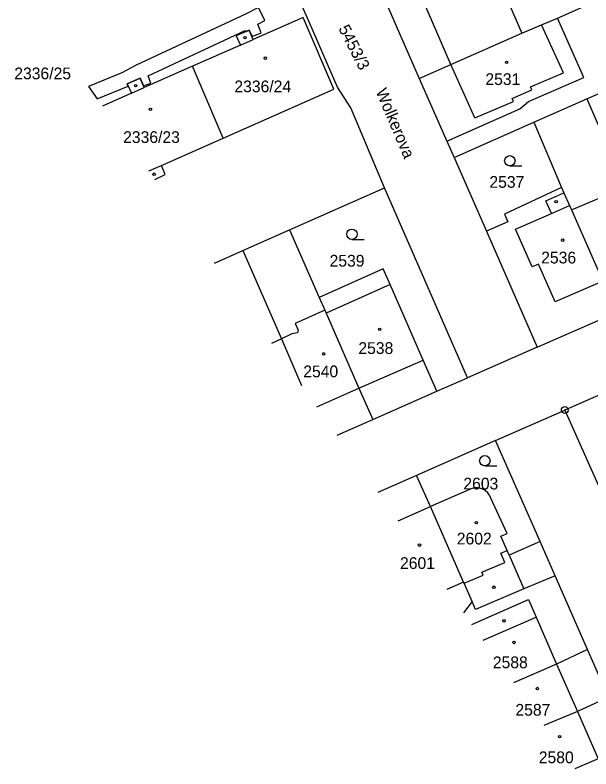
# Model space of a CAD drawing. Extents: x -821458 to -820266, y -1071458 to -1069826.
# Drawn here: x -820847.1 to -820763.7, y -1071320.8 to -1071211.7 of the extents above; entities that cross this region are included whole.
import ezdxf

# ---------------------------------------------------------------- set-up
doc = ezdxf.new("R2010")
doc.units = 0
for name, color, linetype in [('Vrstva 1', 7, 'Continuous'), ('Vrstva 13', 7, 'Continuous'), ('Vrstva 2', 7, 'Continuous'), ('Vrstva 3', 7, 'Continuous'), ('Vrstva 4', 7, 'Continuous'), ('Vrstva 5', 7, 'Continuous'), ('Vrstva 7', 7, 'Continuous'), ('Vrstva 8', 7, 'Continuous')]:
    doc.layers.add(name, color=color, linetype=linetype)

msp = doc.modelspace()

# ---------------------------------------------------------------- linework, layer by layer
at = {"layer": 'Vrstva 1'}
for p, q in [((-820783.95, -1071218.81), (-820790.93, -1071202.76)), ((-820768.53, -1071212.08), (-820752.85, -1071205.14)), ((-820783.95, -1071218.81), (-820773.66, -1071214.29)), ((-820816.91, -1071229.46), (-820821.37, -1071219.04)), ((-820788.57, -1071220.85), (-820783.95, -1071218.81)), ((-820788.57, -1071220.85), (-820784.55, -1071229.93)), ((-820764.28, -1071223.77), (-820757.43, -1071220.74)), ((-820771.93, -1071227.16), (-820764.28, -1071223.77)), ((-820783.5, -1071232.29), (-820771.93, -1071227.16)), ((-820771.93, -1071227.16), (-820767.92, -1071236.61)), ((-820784.55, -1071229.93), (-820783.5, -1071232.29)), ((-820783.5, -1071232.29), (-820778.81, -1071242.96)), ((-820807.32, -1071242.73), (-820793.58, -1071236.65)), ((-820781.53, -1071264.15), (-820793.58, -1071236.65)), ((-820814.1, -1071245.75), (-820807.32, -1071242.73)), ((-820807.32, -1071242.73), (-820803.01, -1071252.53)), ((-820778.81, -1071242.96), (-820771.47, -1071259.73)), ((-820818.19, -1071247.56), (-820814.1, -1071245.75)), ((-820771.47, -1071259.73), (-820759.98, -1071254.72)), ((-820771.47, -1071259.73), (-820781.53, -1071264.15)), ((-820749.12, -1071260.8), (-820767.46, -1071268.84)), ((-820786.01, -1071266.12), (-820781.53, -1071264.15)), ((-820795.25, -1071270.19), (-820786.01, -1071266.12)), ((-820777.49, -1071273.25), (-820767.46, -1071268.84)), ((-820767.46, -1071268.84), (-820760.37, -1071284.81)), ((-820800.44, -1071272.47), (-820795.25, -1071270.19)), ((-820777.49, -1071273.25), (-820788.93, -1071278.29)), ((-820771.05, -1071287.86), (-820777.49, -1071273.25)), ((-820788.93, -1071278.29), (-820794.53, -1071280.76)), ((-820786.92, -1071282.82), (-820788.93, -1071278.29)), ((-820781.01, -1071280.22), (-820786.92, -1071282.82)), ((-820768.86, -1071292.83), (-820771.05, -1071287.86)), ((-820764.16, -1071303.5), (-820768.86, -1071292.83)), ((-820780.88, -1071296.55), (-820782.11, -1071298.19)), ((-820761.12, -1071310.4), (-820764.16, -1071303.5))]:
    msp.add_line(p, q, dxfattribs=at)
for points in [[(-820796.98, -1071151.09), (-820799.19, -1071153.08), (-820801.78, -1071155.4), (-820804.28, -1071158.47), (-820806.33, -1071161.63), (-820807.71, -1071165.19), (-820808.34, -1071171.22), (-820808.11, -1071173.69), (-820807.37, -1071176.5), (-820806.77, -1071178.58), (-820806.01, -1071180.77), (-820788.57, -1071220.85)], [(-820793.58, -1071236.65), (-820798.44, -1071225.1), (-820800.39, -1071222.09), (-820804.84, -1071211.76), (-820807.79, -1071205.27), (-820809.61, -1071200.07), (-820811.76, -1071194.82), (-820812.77, -1071194.08), (-820813.94, -1071193.87), (-820836.17, -1071203.63), (-820846.32, -1071208.08)], [(-820780.65, -1071198.21), (-820777.6, -1071205.22), (-820776.77, -1071207.14), (-820773.66, -1071214.29)], [(-820816.91, -1071229.46), (-820800.9, -1071222.39), (-820805.35, -1071211.99), (-820812.57, -1071215.18), (-820813.16, -1071213.83), (-820815.03, -1071214.64), (-820814.43, -1071216), (-820821.37, -1071219.04)], [(-820784.55, -1071229.93), (-820773.96, -1071225.23), (-820772.71, -1071224.15), (-820764.69, -1071220.67), (-820768.53, -1071212.08)], [(-820773.66, -1071214.29), (-820770.82, -1071213.09), (-820768.53, -1071212.08)], [(-820821.37, -1071219.04), (-820828.34, -1071222.14), (-820828.93, -1071220.8), (-820830.81, -1071221.62), (-820830.21, -1071222.97), (-820834.4, -1071224.82)], [(-820764.28, -1071223.77), (-820759.48, -1071234.8), (-820754.18, -1071246.75), (-820752.2, -1071251.29)], [(-820826.81, -1071235.46), (-820825.31, -1071234.75), (-820825.87, -1071233.42), (-820816.91, -1071229.46)], [(-820767.92, -1071236.61), (-820776.2, -1071240.49), (-820775.71, -1071241.59), (-820778.81, -1071242.96)], [(-820767.92, -1071236.61), (-820767.59, -1071237.39), (-820766.79, -1071239.2), (-820766.51, -1071239.84), (-820761.95, -1071250.16), (-820759.98, -1071254.72)], [(-820814.1, -1071245.75), (-820808.48, -1071258.54), (-820805.56, -1071265.28)], [(-820786.01, -1071266.12), (-820787.96, -1071261.62), (-820792.74, -1071250.67), (-820793.74, -1071248.39), (-820803.01, -1071252.53)], [(-820803.01, -1071252.53), (-820802.21, -1071254.37), (-820802.01, -1071254.82), (-820797.26, -1071265.69), (-820795.25, -1071270.19)], [(-820778.17, -1071281.6), (-820778.36, -1071281.17), (-820778.63, -1071280.8), (-820778.98, -1071280.49), (-820779.21, -1071280.34), (-820779.64, -1071280.17), (-820780.09, -1071280.08), (-820780.56, -1071280.1), (-820781.01, -1071280.22)], [(-820771.05, -1071287.86), (-820775.51, -1071289.82), (-820775.79, -1071289.18), (-820776.74, -1071287.11), (-820775.83, -1071286.69), (-820778.17, -1071281.6)], [(-820780.88, -1071296.55), (-820782.04, -1071293.91), (-820782.12, -1071293.73), (-820786.92, -1071282.82)], [(-820768.86, -1071292.83), (-820773.37, -1071294.74), (-820780.37, -1071297.7), (-820780.88, -1071296.55)], [(-820764.16, -1071303.5), (-820768.65, -1071305.6), (-820774.91, -1071308.3)], [(-820761.12, -1071310.4), (-820765.64, -1071312.47), (-820770.48, -1071314.51)], [(-820758.1, -1071317.28), (-820762.63, -1071319.34), (-820766.01, -1071320.79)]]:
    msp.add_lwpolyline(points, dxfattribs=at)
at = {"layer": 'Vrstva 13'}
msp.add_line((-820836.4, -1071222), (-820835.15, -1071223.77), dxfattribs=at)
msp.add_lwpolyline([(-820835.15, -1071223.77), (-820830.67, -1071221.93), (-820830.81, -1071221.62), (-820828.93, -1071220.8), (-820828.46, -1071221.88), (-820827.39, -1071221.49), (-820827.77, -1071220.43), (-820813.76, -1071213.89), (-820813.69, -1071214.06), (-820813.16, -1071213.83), (-820812.75, -1071214.77), (-820811.4, -1071214.23), (-820811.9, -1071212.98), (-820810.87, -1071212.46), (-820811.83, -1071210.58), (-820813.68, -1071211.52), (-820829.54, -1071218.93), (-820831.6, -1071220.03), (-820836.4, -1071222)], dxfattribs=at)
at = {"layer": 'Vrstva 3'}
for p, q in [((-820775.42, -1071233.5), (-820773.67, -1071233.5)), ((-820798.28, -1071244.14), (-820796.53, -1071244.14)), ((-820779.04, -1071276.92), (-820777.29, -1071276.92))]:
    msp.add_line(p, q, dxfattribs=at)
for centre in [(-820775.42, -1071232.75), (-820798.28, -1071243.39), (-820779.04, -1071276.17)]:
    msp.add_circle(centre, 0.75, dxfattribs=at)
at = {"layer": 'Vrstva 4'}
for p, q in [((-820767.67, -1071220.01), (-820770.82, -1071213.09)), ((-820814.43, -1071216), (-820812.57, -1071215.18)), ((-820780.47, -1071226.54), (-820783.95, -1071218.81)), ((-820772.41, -1071222.03), (-820767.67, -1071220.01)), ((-820830.21, -1071222.97), (-820828.34, -1071222.14)), ((-820772.22, -1071222.48), (-820772.41, -1071222.03)), ((-820775.09, -1071223.71), (-820772.22, -1071222.48)), ((-820780.47, -1071226.54), (-820774.9, -1071224.16)), ((-820774.9, -1071224.16), (-820775.09, -1071223.71)), ((-820827.69, -1071234.22), (-820825.87, -1071233.42)), ((-820770.21, -1071238.55), (-820767.59, -1071237.39)), ((-820769.41, -1071240.36), (-820770.21, -1071238.55)), ((-820766.51, -1071239.84), (-820762.48, -1071238.15)), ((-820769.41, -1071240.36), (-820766.79, -1071239.2)), ((-820774.6, -1071242.66), (-820769.41, -1071240.36)), ((-820772.21, -1071248.1), (-820774.6, -1071242.66)), ((-820771.29, -1071247.71), (-820772.21, -1071248.1)), ((-820768.88, -1071253.19), (-820771.29, -1071247.71)), ((-820792.74, -1071250.67), (-820802.01, -1071254.82)), ((-820761.95, -1071250.16), (-820768.88, -1071253.19)), ((-820802.21, -1071254.37), (-820806.51, -1071256.29)), ((-820806.51, -1071256.29), (-820806.07, -1071257.28)), ((-820806.07, -1071257.28), (-820806.17, -1071257.66)), ((-820806.97, -1071257.8), (-820808.48, -1071258.54)), ((-820806.17, -1071257.66), (-820806.97, -1071257.8)), ((-820808.48, -1071258.54), (-820809.91, -1071259.18)), ((-820797.26, -1071265.69), (-820787.96, -1071261.62)), ((-820803.37, -1071268.36), (-820797.26, -1071265.69)), ((-820791.6, -1071284.88), (-820786.92, -1071282.82)), ((-820776.72, -1071289.57), (-820775.79, -1071289.18)), ((-820776.15, -1071290.91), (-820776.72, -1071289.57)), ((-820775.51, -1071289.82), (-820773.37, -1071294.74)), ((-820779.46, -1071292.3), (-820776.15, -1071290.91)), ((-820782.04, -1071293.91), (-820779.28, -1071292.75)), ((-820779.28, -1071292.75), (-820779.46, -1071292.3)), ((-820782.12, -1071293.73), (-820784.53, -1071294.79)), ((-820780.92, -1071299.86), (-820772.74, -1071296.26)), ((-820772.74, -1071296.26), (-820771.62, -1071298.82)), ((-820779.29, -1071302.15), (-820771.62, -1071298.82)), ((-820771.62, -1071298.82), (-820768.65, -1071305.6)), ((-820768.65, -1071305.6), (-820765.64, -1071312.47)), ((-820765.64, -1071312.47), (-820762.63, -1071319.34))]:
    msp.add_line(p, q, dxfattribs=at)
at = {"layer": 'Vrstva 5'}
for centre in [(-820813.78, -1071214.91), (-820810.82, -1071217.89), (-820775.88, -1071218.48), (-820829.6, -1071221.89), (-820827.45, -1071225.31), (-820826.92, -1071234.69), (-820768.71, -1071238.67), (-820767.76, -1071244.24), (-820794.26, -1071257.16), (-820802.39, -1071260.7), (-820780.26, -1071285.12), (-820788.5, -1071288.39), (-820777.74, -1071294.48), (-820776.28, -1071299.35), (-820774.8, -1071302.48), (-820771.43, -1071309.15), (-820768.21, -1071316.1)]:
    msp.add_circle(centre, 0.175, dxfattribs=at)
at = {"layer": 'Vrstva 8'}
for radius in [0.5, 0.0303]:
    msp.add_circle((-820767.46, -1071268.84), radius, dxfattribs=at)

# ---------------------------------------------------------------- texts
at = {"layer": 'Vrstva 2'}
msp.add_text('5453/3', height=1.7, rotation=297, dxfattribs=at).set_placement((-820800.28, -1071213.59))
for s, p in [('2336/25', (-820847.17, -1071220.95)), ('2531', (-820778.96, -1071221.78)), ('2336/24', (-820815.3, -1071222.83)), ('2336/23', (-820831.41, -1071230.17)), ('2537', (-820778.38, -1071236.66)), ('2539', (-820801.52, -1071248.07)), ('2536', (-820770.88, -1071247.61)), ('2538', (-820797.35, -1071260.71)), ('2540', (-820805.33, -1071264.09)), ('2603', (-820782.15, -1071280.33)), ('2602', (-820783.1, -1071288.29)), ('2601', (-820791.32, -1071291.84)), ('2588', (-820777.88, -1071306.21)), ('2587', (-820774.61, -1071313.08)), ('2580', (-820771.23, -1071319.96))]:
    msp.add_text(s, height=1.7, dxfattribs=at).set_placement(p)
at = {"layer": 'Vrstva 7'}
msp.add_text('Wolkerova', height=1.7, rotation=293, dxfattribs=at).set_placement((-820794.88, -1071222.7))

doc.saveas('drawing.dxf')
